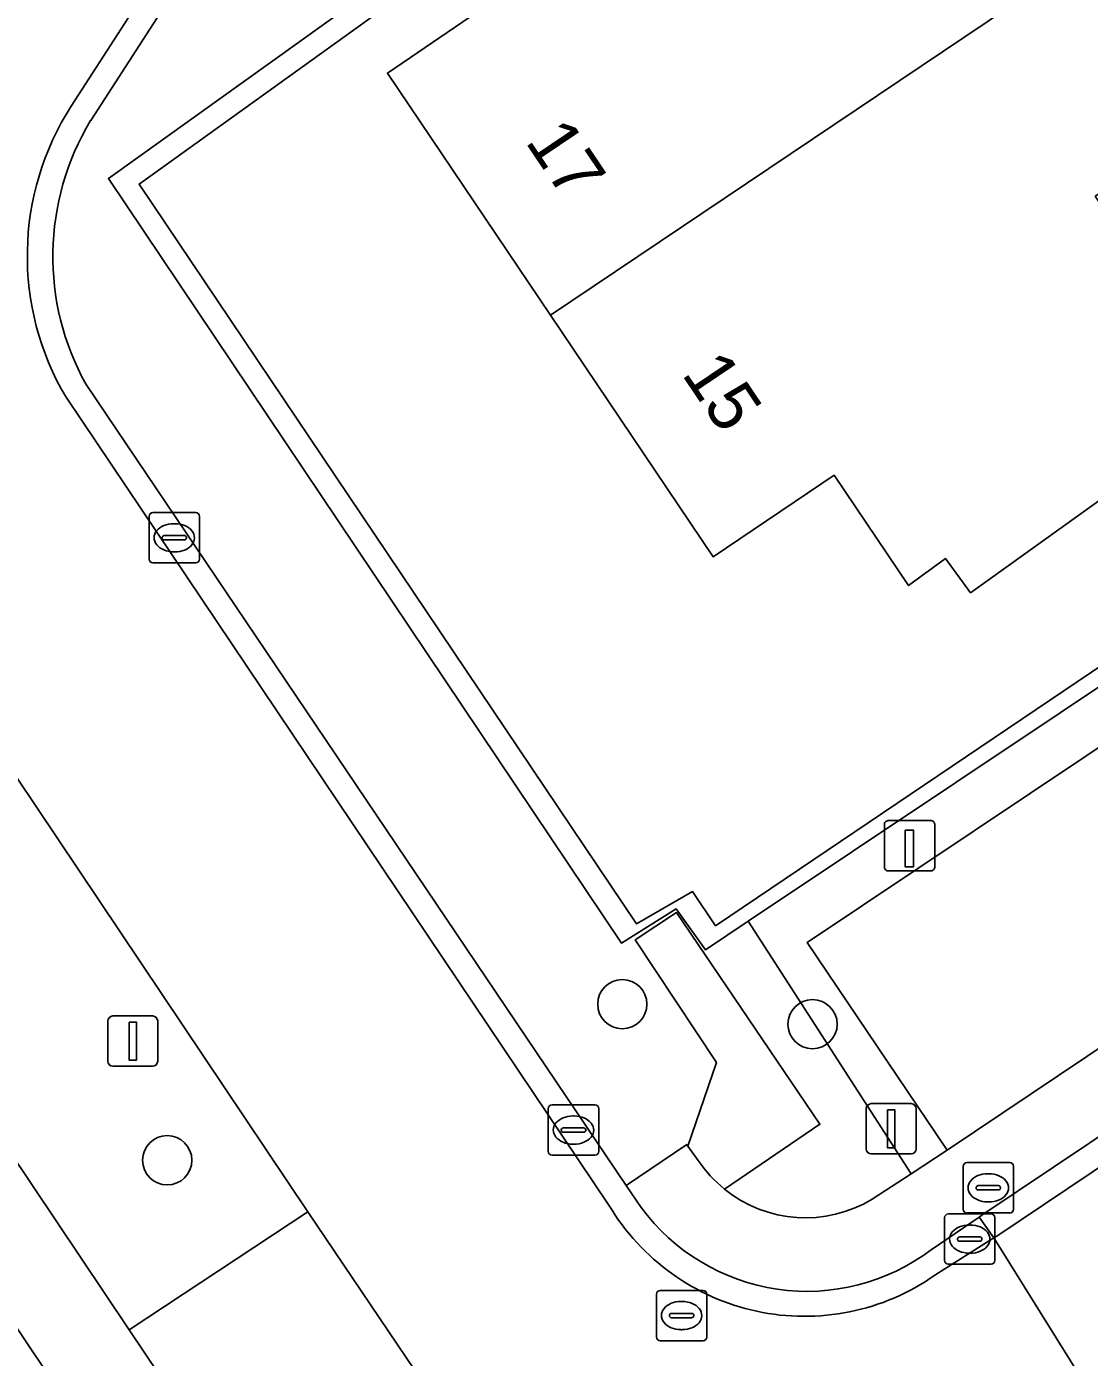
# Model space of a CAD drawing. Extents: x 158793 to 159888, y 384317 to 385256.
# Drawn here: x 158897.57 to 158918.68, y 384617.61 to 384644.03 of the extents above; entities that cross this region are included whole.
import ezdxf

# ---------------------------------------------------------------- set-up
doc = ezdxf.new("R2010")
doc.units = 0
for name, color, linetype in [('IMGEO_Berm_groen', 7, 'Continuous'), ('IMGEO_Boom', 7, 'Continuous'), ('IMGEO_Erf', 7, 'Continuous'), ('IMGEO_Groenvoorziening', 7, 'Continuous'), ('IMGEO_Haag', 7, 'Continuous'), ('IMGEO_Hek', 7, 'Continuous'), ('IMGEO_Kolk', 7, 'Continuous'), ('IMGEO_Laadpaal', 7, 'Continuous'), ('IMGEO_Lichtmast', 7, 'Continuous'), ('IMGEO_Pand', 7, 'Continuous'), ('IMGEO_Pand_nummerreeks', 7, 'Continuous'), ('IMGEO_Parkeervlak_open', 7, 'Continuous'), ('IMGEO_Rijbaan_lokaal_open', 7, 'Continuous'), ('IMGEO_Rioolput', 7, 'Continuous'), ('IMGEO_Voetpad_halfverhard', 7, 'Continuous'), ('IMGEO_Voetpad_open', 7, 'Continuous')]:
    doc.layers.add(name, color=color, linetype=linetype)

msp = doc.modelspace()

# ---------------------------------------------------------------- linework, layer by layer
at = {"layer": 'IMGEO_Berm_groen'}
for points in [[(158912.439, 384663.211), (158898.843, 384642.17)], [(158914.37, 384620.747), (158915.141, 384621.25), (158911.908, 384626.271), (158911.057, 384625.702), (158910.473, 384626.512), (158909.391, 384625.832), (158899.194, 384641.02), (158904.609, 384644.899), (158902.885, 384647.758), (158917.62, 384657.908)], [(158898.752, 384636.926), (158909.484, 384621.018), (158910.684, 384621.834), (158910.708, 384621.801), (158911.273, 384623.463), (158909.663, 384625.896), (158910.484, 384626.44), (158913.33, 384622.237), (158911.433, 384620.949)], [(158892.775, 384636.827), (158888.557, 384636.642), (158887.623, 384636.03), (158899.607, 384618.157), (158903.158, 384620.5), (158894.038, 384634.089)]]:
    msp.add_lwpolyline(points, dxfattribs=at)
for centre, radius, start, end in [((158903.322, 384639.469), 5.231, 148.9156, 209.0961), ((158913.046, 384622.949), 2.57, 231.1192, 301.0119)]:
    msp.add_arc(centre, radius, start, end, dxfattribs=at)
at = {"layer": 'IMGEO_Boom'}
for centre in [(158909.404, 384624.621), (158913.184, 384624.224), (158900.364, 384621.521)]:
    msp.add_circle(centre, 0.489, dxfattribs=at)
at = {"layer": 'IMGEO_Erf'}
for points in [[(158815.511, 384607.239), (158824.8, 384593.502), (158838.699, 384572.93), (158841.845, 384568.15), (158844.791, 384570.111), (158846.183, 384571.037), (158851.961, 384574.901), (158852.64, 384575.355), (158857.172, 384578.386), (158862.362, 384581.922), (158862.863, 384582.253), (158870.987, 384587.696), (158871.33, 384587.937), (158876.65, 384591.488), (158877.708, 384592.194), (158878.556, 384592.76), (158881.626, 384594.81), (158903.507, 384608.931), (158902.593, 384610.317), (158898.058, 384617.173), (158883.161, 384639.419), (158896.259, 384659.409)], [(158924.575, 384644.51), (158926.138, 384642.19), (158930.948, 384645.466), (158934.462, 384640.251), (158927.06, 384635.272), (158926.167, 384636.6), (158925.827, 384636.371), (158925.241, 384637.242), (158922.204, 384635.199), (158920.865, 384637.19), (158919.342, 384636.067), (158919.879, 384635.339), (158916.324, 384632.791), (158915.823, 384633.472), (158915.091, 384632.933), (158913.616, 384635.123), (158911.211, 384633.503), (158907.976, 384638.304), (158904.737, 384643.112), (158907.129, 384644.742)]]:
    msp.add_lwpolyline(points, dxfattribs=at)
msp.add_lwpolyline([(158935.269, 384640.755), (158935.742, 384641.055), (158931.239, 384647.707), (158930.053, 384646.895), (158926.376, 384644.46), (158920.02, 384653.654), (158917.65, 384657.141), (158903.486, 384647.632), (158905.26, 384644.832), (158899.805, 384640.906), (158909.685, 384626.219), (158910.802, 384626.858), (158911.256, 384626.177), (158922.042, 384633.454), (158922.226, 384633.163), (158925.099, 384628.623), (158936.517, 384636.347), (158935.783, 384637.416), (158937.012, 384638.256)], close=True, dxfattribs=at)
at = {"layer": 'IMGEO_Groenvoorziening'}
for points in [[(158917.65, 384657.141), (158917.963, 384657.364), (158917.62, 384657.908), (158902.885, 384647.758), (158904.609, 384644.899), (158899.194, 384641.02), (158909.391, 384625.832), (158910.473, 384626.512), (158911.057, 384625.702), (158911.908, 384626.271), (158922.226, 384633.163), (158922.042, 384633.454), (158911.256, 384626.177), (158910.802, 384626.858), (158909.685, 384626.219), (158899.805, 384640.906), (158905.26, 384644.832), (158903.486, 384647.632)], [(158921.951, 384631.78), (158924.728, 384627.665), (158925.43, 384628.137), (158925.099, 384628.623), (158922.226, 384633.163), (158911.908, 384626.271), (158915.141, 384621.25), (158915.86, 384621.72), (158913.074, 384625.843)]]:
    msp.add_lwpolyline(points, close=True, dxfattribs=at)
at = {"layer": 'IMGEO_Haag'}
msp.add_lwpolyline([(158922.226, 384633.163), (158911.908, 384626.271), (158915.141, 384621.25), (158915.86, 384621.72), (158913.074, 384625.843), (158921.951, 384631.78), (158924.728, 384627.665), (158925.43, 384628.137), (158925.099, 384628.623)], close=True, dxfattribs=at)
at = {"layer": 'IMGEO_Hek'}
msp.add_lwpolyline([(158905.26, 384644.832), (158899.805, 384640.906), (158909.685, 384626.219), (158910.802, 384626.858), (158911.256, 384626.177), (158922.042, 384633.454), (158922.226, 384633.163), (158925.099, 384628.623), (158936.517, 384636.347), (158935.783, 384637.416)], dxfattribs=at)
at = {"layer": 'IMGEO_Kolk'}
for p, q in [((158900.003, 384633.457), (158900.003, 384634.309)), ((158900.078, 384634.383), (158900.93, 384634.383)), ((158901.004, 384634.309), (158901.004, 384633.457)), ((158900.491, 384634.163), (158900.516, 384634.163)), ((158900.262, 384633.877), (158900.262, 384633.889)), ((158900.7, 384633.84), (158900.302, 384633.84)), ((158900.305, 384633.926), (158900.703, 384633.926)), ((158900.746, 384633.889), (158900.746, 384633.877)), ((158900.514, 384633.603), (158900.489, 384633.603)), ((158900.93, 384633.383), (158900.078, 384633.383)), ((158908.009, 384622.621), (158908.861, 384622.621)), ((158907.934, 384621.695), (158907.934, 384622.547)), ((158908.422, 384622.401), (158908.447, 384622.401)), ((158908.935, 384622.547), (158908.935, 384621.695)), ((158908.193, 384622.115), (158908.193, 384622.127)), ((158908.631, 384622.078), (158908.233, 384622.078)), ((158908.236, 384622.164), (158908.634, 384622.164)), ((158908.677, 384622.127), (158908.677, 384622.115)), ((158908.445, 384621.841), (158908.42, 384621.841)), ((158908.861, 384621.621), (158908.009, 384621.621)), ((158915.806, 384619.53), (158915.806, 384620.382)), ((158915.881, 384620.456), (158916.733, 384620.456)), ((158916.294, 384620.236), (158916.319, 384620.236)), ((158916.807, 384620.382), (158916.807, 384619.53)), ((158916.065, 384619.95), (158916.065, 384619.962)), ((158916.108, 384619.999), (158916.506, 384619.999)), ((158916.549, 384619.962), (158916.549, 384619.95)), ((158916.503, 384619.913), (158916.105, 384619.913)), ((158916.733, 384619.456), (158915.881, 384619.456)), ((158916.317, 384619.676), (158916.292, 384619.676))]:
    msp.add_line(p, q, dxfattribs=at)
for points in [[(158900.003, 384633.457), (158900.003, 384634.309)], [(158900.078, 384634.383), (158900.93, 384634.383)], [(158901.004, 384634.309), (158901.004, 384633.457)], [(158900.93, 384633.383), (158900.078, 384633.383)], [(158908.009, 384622.621), (158908.861, 384622.621)], [(158907.934, 384621.695), (158907.934, 384622.547)], [(158908.935, 384622.547), (158908.935, 384621.695)], [(158908.861, 384621.621), (158908.009, 384621.621)], [(158915.806, 384619.53), (158915.806, 384620.382)], [(158915.881, 384620.456), (158916.733, 384620.456)], [(158916.807, 384620.382), (158916.807, 384619.53)], [(158916.733, 384619.456), (158915.881, 384619.456)]]:
    msp.add_lwpolyline(points, dxfattribs=at)
for centre, radius, start, end in [((158900.08, 384634.307), 0.0765, 91.552, 178.448), ((158900.08, 384634.307), 0.0765, 91.552, 178.448), ((158900.928, 384634.307), 0.0765, 1.552, 88.448), ((158900.928, 384634.307), 0.0765, 1.552, 88.448), ((158900.302, 384633.886), 0.0403, 85.8775, 175.7526), ((158900.299, 384633.876), 0.0366, 178.938, 274.7102), ((158900.703, 384633.883), 0.043, 264.8664, 352.4533), ((158900.707, 384633.888), 0.0386, 1.7309, 96.639), ((158900.08, 384633.459), 0.0765, 181.552, 268.448), ((158900.08, 384633.459), 0.0765, 181.552, 268.448), ((158900.928, 384633.459), 0.0765, 271.552, 358.448), ((158900.928, 384633.459), 0.0765, 271.552, 358.448), ((158908.011, 384622.545), 0.0765, 91.552, 178.448), ((158908.011, 384622.545), 0.0765, 91.552, 178.448), ((158908.859, 384622.545), 0.0765, 1.552, 88.448), ((158908.859, 384622.545), 0.0765, 1.552, 88.448), ((158908.233, 384622.124), 0.0403, 85.8775, 175.7526), ((158908.23, 384622.114), 0.0366, 178.938, 274.7102), ((158908.634, 384622.121), 0.043, 264.8664, 352.4533), ((158908.638, 384622.126), 0.0386, 1.7309, 96.639), ((158908.011, 384621.697), 0.0765, 181.552, 268.448), ((158908.011, 384621.697), 0.0765, 181.552, 268.448), ((158908.859, 384621.697), 0.0765, 271.552, 358.448), ((158908.859, 384621.697), 0.0765, 271.552, 358.448), ((158915.883, 384620.38), 0.0765, 91.552, 178.448), ((158915.883, 384620.38), 0.0765, 91.552, 178.448), ((158916.731, 384620.38), 0.0765, 1.552, 88.448), ((158916.731, 384620.38), 0.0765, 1.552, 88.448), ((158916.105, 384619.959), 0.0403, 85.8775, 175.7526), ((158916.51, 384619.961), 0.0386, 1.7309, 96.639), ((158916.102, 384619.949), 0.0366, 178.938, 274.7102), ((158916.506, 384619.956), 0.043, 264.8664, 352.4533), ((158915.883, 384619.532), 0.0765, 181.552, 268.448), ((158915.883, 384619.532), 0.0765, 181.552, 268.448), ((158916.731, 384619.532), 0.0765, 271.552, 358.448), ((158916.731, 384619.532), 0.0765, 271.552, 358.448)]:
    msp.add_arc(centre, radius, start, end, dxfattribs=at)
for centre, major_axis, ratio, start_param, end_param in [((158900.49, 384633.883), (-0.387, 0.002), 0.722429, 4.712389, 7.853982), ((158900.515, 384633.883), (-0.39, 0.002), 0.717154, 1.570796, 4.712389), ((158908.421, 384622.121), (-0.387, 0.002), 0.722429, 4.712389, 7.853982), ((158908.446, 384622.121), (-0.39, 0.002), 0.717154, 1.570796, 4.712389), ((158916.293, 384619.956), (-0.387, 0.002), 0.722429, 4.712389, 7.853982), ((158916.318, 384619.956), (-0.39, 0.002), 0.717154, 1.570796, 4.712389)]:
    msp.add_ellipse(centre, major_axis=major_axis, ratio=ratio, start_param=start_param, end_param=end_param, dxfattribs=at)
at = {"layer": 'IMGEO_Laadpaal'}
for p, q in [((158914.611, 384628.182), (158914.611, 384627.341)), ((158914.611, 384628.182), (158914.611, 384627.341)), ((158915.527, 384628.266), (158914.686, 384628.266)), ((158915.527, 384628.266), (158914.686, 384628.266)), ((158915.611, 384627.35), (158915.611, 384628.191)), ((158915.611, 384627.35), (158915.611, 384628.191)), ((158914.695, 384627.266), (158915.536, 384627.266)), ((158914.695, 384627.266), (158915.536, 384627.266))]:
    msp.add_line(p, q, dxfattribs=at)
msp.add_lwpolyline([(158915.026, 384628.079), (158915.186, 384628.079), (158915.186, 384627.346), (158915.026, 384627.346), (158915.026, 384628.079)], dxfattribs=at)
for centre, start, end in [((158914.689, 384628.188), 92.4484, 184.2845), ((158914.689, 384628.188), 92.4484, 184.2845), ((158915.533, 384628.188), 2.4484, 94.2845), ((158915.533, 384628.188), 2.4484, 94.2845), ((158914.689, 384627.344), 182.4484, 274.2845), ((158914.689, 384627.344), 182.4484, 274.2845), ((158915.533, 384627.344), 272.4484, 4.2845), ((158915.533, 384627.344), 272.4484, 4.2845)]:
    msp.add_arc(centre, 0.0779, start, end, dxfattribs=at)
at = {"layer": 'IMGEO_Lichtmast'}
for p, q in [((158899.185, 384623.487), (158899.185, 384624.287)), ((158899.185, 384624.287), (158899.185, 384623.487)), ((158899.285, 384624.387), (158900.075, 384624.387)), ((158900.075, 384624.387), (158899.285, 384624.387)), ((158900.175, 384624.287), (158900.175, 384623.487)), ((158900.175, 384623.487), (158900.175, 384624.287)), ((158900.075, 384623.387), (158899.285, 384623.387)), ((158899.285, 384623.387), (158900.075, 384623.387)), ((158914.351, 384622.646), (158915.141, 384622.646)), ((158915.141, 384622.646), (158914.351, 384622.646)), ((158914.251, 384621.746), (158914.251, 384622.546)), ((158914.251, 384622.546), (158914.251, 384621.746)), ((158915.241, 384622.546), (158915.241, 384621.746)), ((158915.241, 384621.746), (158915.241, 384622.546)), ((158915.141, 384621.646), (158914.351, 384621.646)), ((158914.351, 384621.646), (158915.141, 384621.646))]:
    msp.add_line(p, q, dxfattribs=at)
for points in [[(158899.605, 384624.262), (158899.755, 384624.262), (158899.755, 384623.512), (158899.605, 384623.512), (158899.605, 384624.262)], [(158914.671, 384622.521), (158914.821, 384622.521), (158914.821, 384621.771), (158914.671, 384621.771), (158914.671, 384622.521)]]:
    msp.add_lwpolyline(points, dxfattribs=at)
for centre, start, end in [((158899.285, 384624.287), 90, 180), ((158899.285, 384624.287), 90, 180), ((158900.075, 384624.287), 0, 90), ((158900.075, 384624.287), 360, 90), ((158899.285, 384623.487), 180, 270), ((158899.285, 384623.487), 180, 270), ((158900.075, 384623.487), 270, 0), ((158900.075, 384623.487), 270, 0), ((158914.351, 384622.546), 90, 180), ((158914.351, 384622.546), 90, 180), ((158915.141, 384622.546), 0, 90), ((158915.141, 384622.546), 360, 90), ((158914.351, 384621.746), 180, 270), ((158914.351, 384621.746), 180, 270), ((158915.141, 384621.746), 270, 0), ((158915.141, 384621.746), 270, 0)]:
    msp.add_arc(centre, 0.1, start, end, dxfattribs=at)
at = {"layer": 'IMGEO_Pand'}
for points in [[(158922.28, 384647.917), (158919.852, 384651.521), (158916.47, 384649.231), (158914.28, 384652.511), (158905.762, 384646.758), (158907.129, 384644.742), (158904.737, 384643.112), (158907.976, 384638.304)], [(158918.797, 384640.665), (158924.575, 384644.51), (158922.28, 384647.917), (158907.976, 384638.304), (158911.211, 384633.503), (158913.616, 384635.123), (158915.091, 384632.933), (158915.823, 384633.472), (158916.324, 384632.791), (158919.879, 384635.339), (158919.342, 384636.067), (158920.865, 384637.19), (158921.037, 384637.317)]]:
    msp.add_lwpolyline(points, close=True, dxfattribs=at)
at = {"layer": 'IMGEO_Parkeervlak_open'}
msp.add_lwpolyline([(158924.728, 384627.665), (158921.951, 384631.78), (158913.074, 384625.843), (158915.86, 384621.72)], close=True, dxfattribs=at)
at = {"layer": 'IMGEO_Rijbaan_lokaal_open'}
for points in [[(158920.527, 384663.541), (158921.052, 384662.795), (158921.38, 384662.329), (158923.499, 384659.163), (158924.01, 384658.409), (158927.045, 384653.945), (158927.544, 384653.21), (158930.702, 384648.501), (158931.239, 384647.707), (158935.742, 384641.055), (158937.439, 384638.548), (158937.764, 384638.068), (158939.325, 384635.681), (158916.548, 384620.432), (158916.491, 384620.393), (158916.788, 384619.978), (158916.847, 384620.015), (158940.033, 384635.577), (158921.019, 384663.762)], [(158921.019, 384663.762), (158940.033, 384635.577), (158916.847, 384620.015), (158916.788, 384619.978), (158918.623, 384617.027), (158918.871, 384617.212), (158941.972, 384632.67)], [(158912.439, 384663.211), (158912.025, 384663.435), (158898.456, 384642.456)], [(158898.456, 384642.456), (158912.025, 384663.435)], [(158898.843, 384642.17), (158912.439, 384663.211)], [(158909.78, 384620.584), (158909.484, 384621.018), (158898.752, 384636.926)], [(158898.353, 384636.673), (158909.14, 384620.629)], [(158909.14, 384620.629), (158898.353, 384636.673)], [(158894.038, 384634.089), (158903.158, 384620.5), (158906.885, 384614.978), (158907.727, 384613.741)], [(158915.614, 384619.237), (158916.788, 384619.978), (158916.491, 384620.393), (158915.538, 384619.745)], [(158917.694, 384616.333), (158918.623, 384617.027), (158916.788, 384619.978), (158915.614, 384619.237)]]:
    msp.add_lwpolyline(points, dxfattribs=at)
for centre, radius, start, end in [((158903.095, 384639.481), 5.511, 147.3249, 210.6344), ((158903.095, 384639.481), 5.511, 147.3249, 210.6344), ((158903.322, 384639.469), 5.231, 148.9156, 209.0961), ((158913.024, 384622.943), 4.521, 210.7812, 304.9495), ((158913.024, 384622.943), 4.521, 210.7812, 304.9495), ((158913.073, 384623.005), 4.087, 216.322, 307.0975)]:
    msp.add_arc(centre, radius, start, end, dxfattribs=at)
at = {"layer": 'IMGEO_Rioolput'}
for p, q in [((158916.175, 384620.548), (158916.175, 384621.4)), ((158916.25, 384621.474), (158917.102, 384621.474)), ((158917.176, 384621.4), (158917.176, 384620.548)), ((158916.663, 384621.254), (158916.688, 384621.254)), ((158916.434, 384620.968), (158916.434, 384620.98)), ((158916.872, 384620.931), (158916.474, 384620.931)), ((158916.477, 384621.017), (158916.875, 384621.017)), ((158916.918, 384620.98), (158916.918, 384620.968)), ((158916.686, 384620.694), (158916.661, 384620.694)), ((158917.102, 384620.474), (158916.25, 384620.474)), ((158910.157, 384618.937), (158911.009, 384618.937)), ((158910.082, 384618.011), (158910.082, 384618.863)), ((158910.57, 384618.717), (158910.595, 384618.717)), ((158911.083, 384618.863), (158911.083, 384618.011)), ((158910.341, 384618.431), (158910.341, 384618.443)), ((158910.779, 384618.394), (158910.381, 384618.394)), ((158910.384, 384618.48), (158910.782, 384618.48)), ((158910.825, 384618.443), (158910.825, 384618.431)), ((158910.593, 384618.157), (158910.568, 384618.157)), ((158911.009, 384617.937), (158910.157, 384617.937))]:
    msp.add_line(p, q, dxfattribs=at)
for points in [[(158916.175, 384620.548), (158916.175, 384621.4)], [(158916.25, 384621.474), (158917.102, 384621.474)], [(158917.176, 384621.4), (158917.176, 384620.548)], [(158917.102, 384620.474), (158916.25, 384620.474)], [(158910.157, 384618.937), (158911.009, 384618.937)], [(158910.082, 384618.011), (158910.082, 384618.863)], [(158911.083, 384618.863), (158911.083, 384618.011)], [(158911.009, 384617.937), (158910.157, 384617.937)]]:
    msp.add_lwpolyline(points, dxfattribs=at)
for centre, radius, start, end in [((158916.252, 384621.398), 0.0765, 91.552, 178.448), ((158916.252, 384621.398), 0.0765, 91.552, 178.448), ((158917.1, 384621.398), 0.0765, 1.552, 88.448), ((158917.1, 384621.398), 0.0765, 1.552, 88.448), ((158916.879, 384620.979), 0.0386, 1.7309, 96.639), ((158916.474, 384620.977), 0.0403, 85.8775, 175.7526), ((158916.471, 384620.967), 0.0366, 178.938, 274.7102), ((158916.875, 384620.974), 0.043, 264.8664, 352.4533), ((158916.252, 384620.55), 0.0765, 181.552, 268.448), ((158916.252, 384620.55), 0.0765, 181.552, 268.448), ((158917.1, 384620.55), 0.0765, 271.552, 358.448), ((158917.1, 384620.55), 0.0765, 271.552, 358.448), ((158910.159, 384618.861), 0.0765, 91.552, 178.448), ((158910.159, 384618.861), 0.0765, 91.552, 178.448), ((158911.007, 384618.861), 0.0765, 1.552, 88.448), ((158911.007, 384618.861), 0.0765, 1.552, 88.448), ((158910.381, 384618.44), 0.0403, 85.8775, 175.7526), ((158910.378, 384618.43), 0.0366, 178.938, 274.7102), ((158910.782, 384618.437), 0.043, 264.8664, 352.4533), ((158910.786, 384618.442), 0.0386, 1.7309, 96.639), ((158910.159, 384618.013), 0.0765, 181.552, 268.448), ((158910.159, 384618.013), 0.0765, 181.552, 268.448), ((158911.007, 384618.013), 0.0765, 271.552, 358.448), ((158911.007, 384618.013), 0.0765, 271.552, 358.448)]:
    msp.add_arc(centre, radius, start, end, dxfattribs=at)
for centre, major_axis, ratio, start_param, end_param in [((158916.662, 384620.974), (-0.387, 0.002), 0.722429, 4.712389, 7.853982), ((158916.687, 384620.974), (-0.39, 0.002), 0.717154, 1.570796, 4.712389), ((158910.569, 384618.437), (-0.387, 0.002), 0.722429, 4.712389, 7.853982), ((158910.594, 384618.437), (-0.39, 0.002), 0.717154, 1.570796, 4.712389)]:
    msp.add_ellipse(centre, major_axis=major_axis, ratio=ratio, start_param=start_param, end_param=end_param, dxfattribs=at)
at = {"layer": 'IMGEO_Voetpad_halfverhard'}
for points in [[(158911.433, 384620.949), (158913.33, 384622.237), (158910.484, 384626.44), (158909.663, 384625.896), (158911.273, 384623.463), (158910.708, 384621.801)], [(158910.708, 384621.801), (158910.912, 384621.519)]]:
    msp.add_lwpolyline(points, dxfattribs=at)
msp.add_arc((158913.036, 384622.937), 2.553, 213.7308, 231.126, dxfattribs=at)
at = {"layer": 'IMGEO_Voetpad_open'}
for points in [[(158903.319, 384612.632), (158899.607, 384618.157), (158887.623, 384636.03), (158887.066, 384636.861), (158886.755, 384640.837), (158886.715, 384641.342), (158896.873, 384656.771), (158898.433, 384655.769), (158900.568, 384659.041), (158902.408, 384657.762), (158904.546, 384661.066), (158901.084, 384663.437), (158907.828, 384673.873), (158914.233, 384683.849), (158920.408, 384693.282)], [(158912.641, 384684.801), (158897.345, 384661.12), (158898.939, 384660.023), (158897.847, 384658.378), (158896.259, 384659.409), (158883.161, 384639.419), (158898.058, 384617.173)], [(158939.325, 384635.681), (158937.764, 384638.068), (158936.543, 384637.243), (158937.281, 384636.103), (158925.43, 384628.137), (158924.728, 384627.665), (158915.86, 384621.72), (158915.141, 384621.25), (158914.37, 384620.747)], [(158915.538, 384619.745), (158916.491, 384620.393), (158916.548, 384620.432), (158939.325, 384635.681)], [(158910.912, 384621.519), (158910.708, 384621.801), (158910.684, 384621.834), (158909.484, 384621.018), (158909.78, 384620.584)]]:
    msp.add_lwpolyline(points, dxfattribs=at)
msp.add_lwpolyline([(158903.158, 384620.5), (158899.607, 384618.157), (158903.319, 384612.632), (158906.885, 384614.978)], close=True, dxfattribs=at)
for centre, radius, start, end in [((158913.036, 384622.937), 2.553, 213.7308, 231.126), ((158913.046, 384622.949), 2.57, 231.1192, 301.0119), ((158913.073, 384623.005), 4.087, 216.322, 307.0975)]:
    msp.add_arc(centre, radius, start, end, dxfattribs=at)

# ---------------------------------------------------------------- texts
at = {"layer": 'IMGEO_Pand_nummerreeks'}
for s, rotation, p in [('17', 303.968, (158907.461, 384641.752)), ('15', 303.9705, (158910.57, 384637.138))]:
    msp.add_text(s, height=1, rotation=rotation, dxfattribs=at).set_placement(p)

doc.saveas('drawing.dxf')
